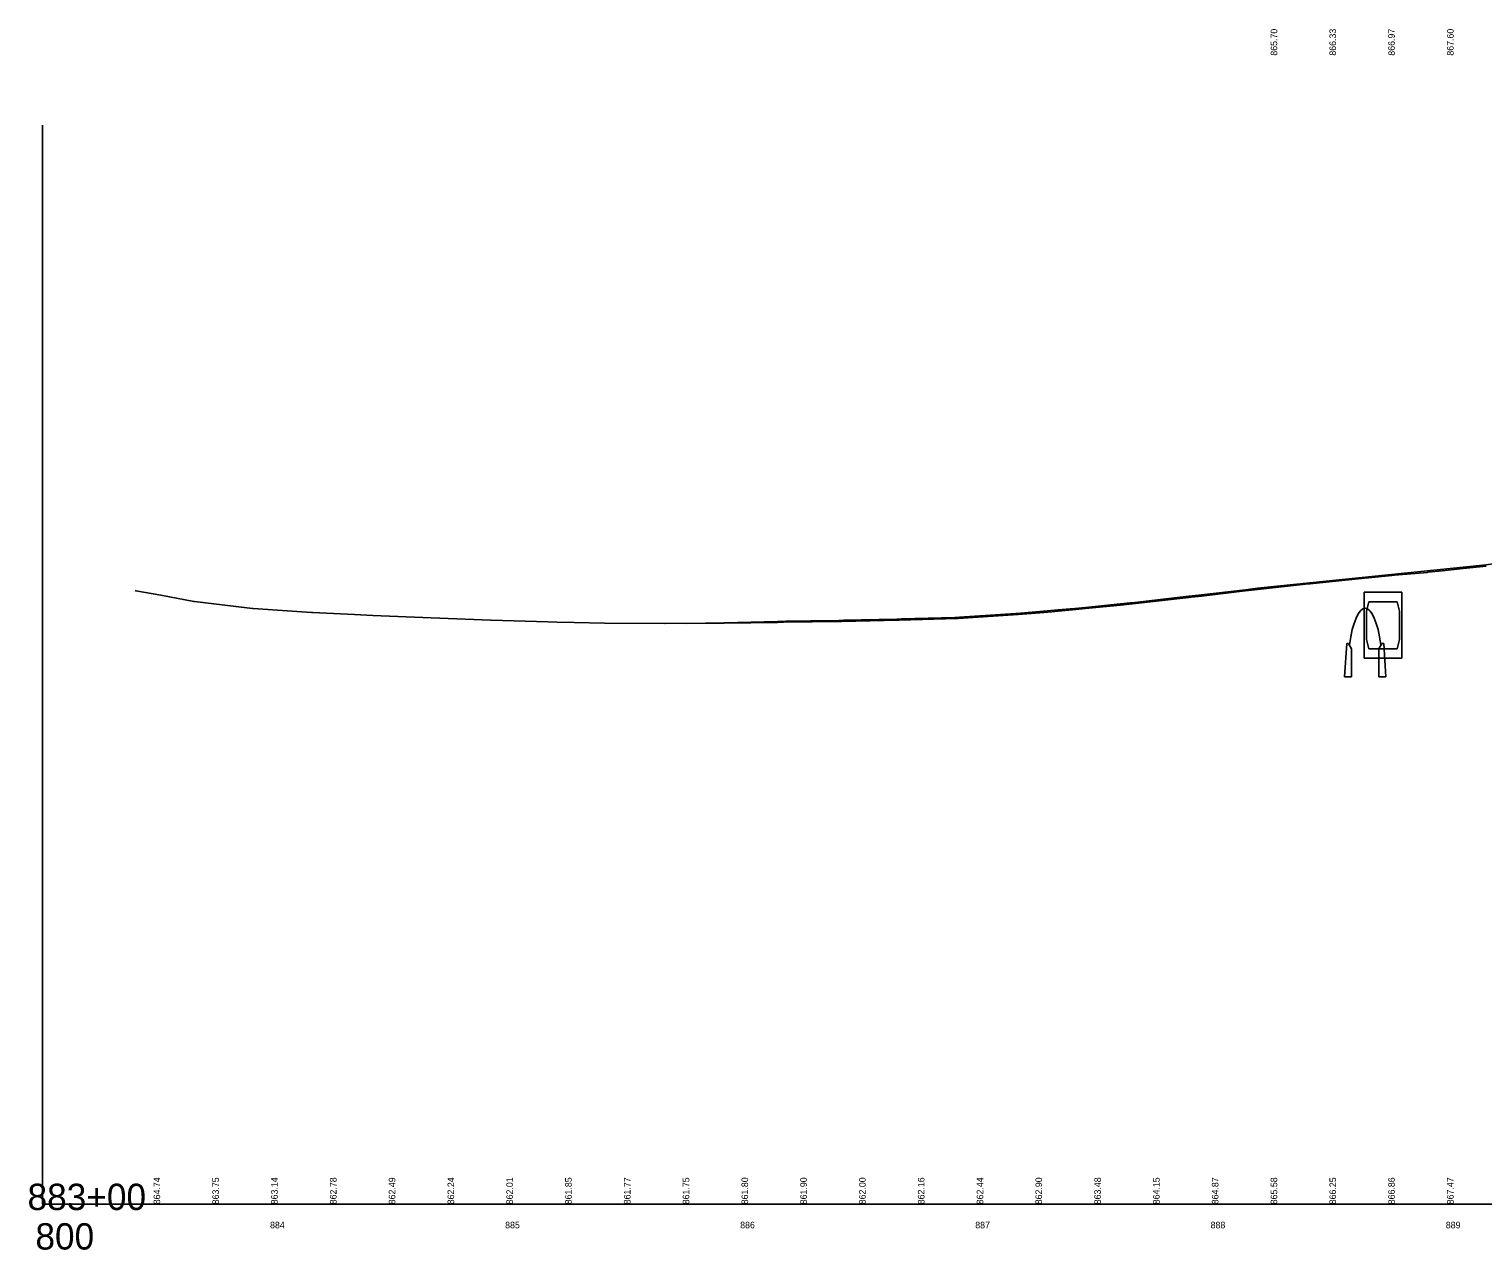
# Model space of a CAD drawing. Extents: x 223098 to 226975, y 386666 to 387582.
# Drawn here: x 225752 to 226370, y 387063 to 387582 of the extents above; entities that cross this region are included whole.
import ezdxf

# ---------------------------------------------------------------- set-up
doc = ezdxf.new("R2010")
doc.units = 0
for name, color, linetype in [('_CIVIL_CONSTRUCTION', 7, 'Continuous'), ('GE_P_Alignment_100_Bearings', 7, 'Continuous'), ('GE_P_Alignment_100_Distances', 7, 'Continuous'), ('GE_P_Alignment_100_Stations', 7, 'Continuous'), ('PV_X_Shoulder_Aggregate', 7, 'Continuous'), ('RD_X_Fence', 7, 'Continuous')]:
    doc.layers.add(name, color=color, linetype=linetype)

msp = doc.modelspace()

# ---------------------------------------------------------------- linework, layer by layer
at = {"layer": '_CIVIL_CONSTRUCTION'}
for p, q in [((226312.5, 387320.49), (226311.54, 387306.21)), ((226312.5, 387320.49), (226313.34, 387320.49)), ((226314.54, 387318.21), (226313.34, 387320.49)), ((226314.54, 387306.21), (226314.54, 387318.21)), ((226326.22, 387318.21), (226327.43, 387320.49)), ((226326.22, 387306.21), (226326.22, 387318.21)), ((226328.26, 387320.49), (226327.43, 387320.49)), ((226328.26, 387320.49), (226329.22, 387306.21)), ((226311.54, 387306.21), (226314.54, 387306.21)), ((226329.22, 387306.21), (226326.22, 387306.21))]:
    msp.add_line(p, q, dxfattribs=at)
msp.add_ellipse((226320.38, 387304.4), major_axis=(0, 31), ratio=0.25, start_param=5.234798, end_param=7.331572, dxfattribs=at)
at = {"layer": 'GE_P_Alignment_100_Bearings'}
msp.add_lwpolyline([(225797.36, 387342.95), (225797.63, 387342.89), (225808.22, 387340.93), (225822.23, 387338.31), (225822.57, 387338.25), (225847.27, 387335.3), (225847.53, 387335.27), (225872.32, 387333.63), (225872.55, 387333.62), (225872.78, 387333.61), (225890.68, 387332.73), (225898.4, 387332.34), (225898.42, 387332.34), (225923.16, 387331.35), (225923.25, 387331.34), (225948.63, 387330.35), (225948.71, 387330.34), (225972.8, 387329.61), (225976.61, 387329.54), (225983.99, 387329.39), (225996.95, 387329.14), (226022.61, 387328.99), (226022.78, 387328.99), (226047.51, 387329.02), (226047.67, 387329.02), (226047.84, 387329.03), (226070.52, 387329.43), (226073.03, 387329.47), (226073.05, 387329.47), (226097.54, 387329.78), (226097.63, 387329.78), (226121.96, 387330.33), (226122.16, 387330.34), (226146.91, 387331.08), (226147.13, 387331.09), (226147.35, 387331.1), (226172.76, 387332.73), (226172.82, 387332.74), (226182.03, 387333.53), (226187.13, 387333.97), (226189.86, 387334.21), (226195.96, 387334.73), (226201.42, 387335.28), (226216.27, 387336.77), (226221.3, 387337.27), (226221.39, 387337.28), (226245.41, 387340), (226246.33, 387340.1), (226246.41, 387340.11), (226250.81, 387340.63), (226270.43, 387342.94), (226270.76, 387342.97), (226274.55, 387343.4), (226296.2, 387345.75), (226296.62, 387345.79), (226297.03, 387345.83), (226303.7, 387346.55), (226321.57, 387348.37), (226321.81, 387348.39), (226331.77, 387349.33), (226332.84, 387349.43), (226334.48, 387349.58), (226346.83, 387350.69), (226347.02, 387350.71), (226353.07, 387351.37), (226361.98, 387352.33), (226371.76, 387353.36)], dxfattribs=at)
at = {"layer": 'GE_P_Alignment_100_Distances'}
for q in [(225757.98, 387540.89), (226975.39, 387082)]:
    msp.add_line((225757.98, 387082), q, dxfattribs=at)
at = {"layer": 'GE_P_Alignment_100_Stations'}
for p, q in [((226282.98, 387344.81), (226357.98, 387352.4)), ((226269.43, 387343.32), (226271.42, 387343.55)), ((226220.39, 387337.68), (226222.38, 387337.89)), ((226074.03, 387329.88), (226072.03, 387329.83)), ((226084.48, 387330.12), (226074.03, 387329.88)), ((226084.48, 387330.12), (226096.54, 387330.27)), ((226096.54, 387330.27), (226098.54, 387330.3)), ((226098.54, 387330.3), (226121.16, 387330.81)), ((226121.16, 387330.81), (226123.16, 387330.87)), ((226123.16, 387330.87), (226145.91, 387331.55)), ((226145.91, 387331.55), (226147.91, 387331.64)), ((226147.91, 387331.64), (226171.77, 387333.17)), ((226171.77, 387333.17), (226173.76, 387333.32)), ((226194.97, 387335.14), (226196.96, 387335.33))]:
    msp.add_line(p, q, dxfattribs=at)
for points in [[(226357.98, 387352.4), (226361.98, 387352.83), (226371.76, 387353.86), (226391.12, 387356.77), (226395.93, 387357.48), (226420.26, 387362.7), (226422.21, 387363.12), (226446.78, 387370.85), (226471.4, 387380.52), (226496.6, 387391.87), (226521.29, 387403.01), (226544.22, 387412.97), (226553.48, 387416.64)], [(226222.38, 387337.89), (226245.41, 387340.5), (226250.81, 387341.13), (226269.43, 387343.32)], [(226271.42, 387343.55), (226274.55, 387343.9), (226282.98, 387344.81)], [(226196.96, 387335.33), (226201.42, 387335.78), (226216.27, 387337.27), (226220.39, 387337.68)], [(226072.03, 387329.83), (226070.52, 387329.79), (226047.84, 387329.18), (226031.98, 387329)], [(226173.76, 387333.32), (226182.03, 387334.03), (226189.86, 387334.71), (226194.97, 387335.14)]]:
    msp.add_lwpolyline(points, dxfattribs=at)
at = {"layer": 'PV_X_Shoulder_Aggregate'}
for p, q in [((226319.98, 387342.2), (226319.98, 387314.2)), ((226319.98, 387342.2), (226335.98, 387342.2)), ((226335.98, 387342.2), (226335.98, 387314.2)), ((226321.98, 387338.2), (226320.98, 387334.2)), ((226333.98, 387338.2), (226321.98, 387338.2)), ((226334.98, 387334.2), (226333.98, 387338.2)), ((226320.98, 387334.2), (226320.98, 387322.2)), ((226334.98, 387322.2), (226334.98, 387334.2)), ((226320.98, 387322.2), (226321.98, 387318.2)), ((226321.98, 387318.2), (226333.98, 387318.2)), ((226333.98, 387318.2), (226334.98, 387322.2)), ((226319.98, 387314.2), (226335.98, 387314.2))]:
    msp.add_line(p, q, dxfattribs=at)

# ---------------------------------------------------------------- texts
at = {"layer": 'GE_P_Alignment_100_Distances'}
for s, p in [('883+00', (225751.59, 387079.56)), ('800', (225754.93, 387062.76))]:
    msp.add_text(s, height=11.2, dxfattribs=at).set_placement(p)
at = {"layer": 'RD_X_Fence'}
for s, p in [('865.70', (226282.98, 387570.37)), ('866.33', (226307.98, 387570.37)), ('866.97', (226332.98, 387570.37)), ('867.60', (226357.98, 387570.37)), ('864.74', (225807.98, 387082)), ('863.75', (225832.98, 387082)), ('863.14', (225857.98, 387082)), ('862.78', (225882.98, 387082)), ('862.49', (225907.98, 387082)), ('862.24', (225932.98, 387082)), ('862.01', (225957.98, 387082)), ('861.85', (225982.98, 387082)), ('861.77', (226007.98, 387082)), ('861.75', (226032.98, 387082)), ('861.80', (226057.98, 387082)), ('861.90', (226082.98, 387082)), ('862.00', (226107.98, 387082)), ('862.16', (226132.98, 387082)), ('862.44', (226157.98, 387082)), ('862.90', (226182.98, 387082)), ('863.48', (226207.98, 387082)), ('864.15', (226232.98, 387082)), ('864.87', (226257.98, 387082)), ('865.58', (226282.98, 387082)), ('866.25', (226307.98, 387082)), ('866.86', (226332.98, 387082)), ('867.47', (226357.98, 387082))]:
    msp.add_text(s, height=2.8, rotation=90, dxfattribs=at).set_placement(p)
for s, p in [('884', (225854.71, 387071.78)), ('885', (225954.68, 387071.78)), ('886', (226054.62, 387071.78)), ('887', (226154.57, 387071.78)), ('888', (226254.65, 387071.78)), ('889', (226354.66, 387071.78))]:
    msp.add_text(s, height=2.8, dxfattribs=at).set_placement(p)

doc.saveas('drawing.dxf')
